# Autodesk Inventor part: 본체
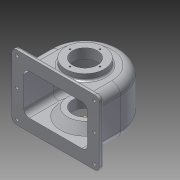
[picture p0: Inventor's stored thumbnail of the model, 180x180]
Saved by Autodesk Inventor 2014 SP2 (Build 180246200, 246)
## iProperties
Created: 2015-09
Part Number: 본체
Material: 알루미늄 6061
Document SubType Name: Modeling
Designer: 201-01
Density: 2.71 g/cm^3
Appearance: 알루미늄 - 평지
Mass: 756.01 g
Surface Area: 887.831 cm^2
Volume: 278.97 cm^3
Author: 201-01
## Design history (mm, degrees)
sketch "스케치1"
  geometry: L1 (-79.8, 0)-(79.8, 0) reference; L2 (0, -67.8)-(0, 77.8) reference; L3 (57, 0)-(57, -47); L4 (57, -47)-(-57, -47); L5 (-57, -47)-(-57, 0); A1 r 57 centre (0, 0) between (57, 0) and (-57, 0); 1 further point
  constraints: 6 end point, 2 coincident, 2 parallel, 2 point on circle, 2 tangent, 1 centre point, 1 perpendicular
  dimensions: "d1" = 47 distance of L3.start L3.end; "d2" = 57 radius of A1
extrude "돌출1" new body sketch "스케치1" distance "d3" = 77; taper "d4" = 0 deg
feature "쉘1" dims "d5" = 6
sketch "스케치2"
  geometry: C1 r 31 at (0, 0); 1 further point
  constraints: 1 centre point, 1 coincident
  dimensions: "d6" = 62 diameter of C1
extrude "돌출2" join sketch "스케치2" distance "d7" = 10; taper "d8" = 0 deg
hole "구멍1" diameter "d11" = 40; stored, may be unused: countersink angle "d15" = 90 deg, drill point angle "d17" = 0 deg; dims "d9" = 10, "d10" = 10, "d12" = 6, "d13" = 4, "d14" = 2, "d16" = 20
sketch "스케치3"
  geometry: C1 r 28 at (0, 0); 1 further point
  constraints: 1 centre point, 1 coincident
  dimensions: "d18" = 56 diameter of C1
extrude "돌출3" join sketch "스케치3" distance "d19" = 19; taper "d20" = 0 deg
feature "면 기울기2" dims angle "d47" = 40 deg
hole "구멍2" diameter "d50" = 40; stored, may be unused: countersink angle "d54" = 90 deg, drill point angle "d56" = 0 deg; dims "d48" = 10, "d49" = 10, "d51" = 6, "d52" = 4, "d53" = 2, "d55" = 20
hole "구멍3" diameter "d59" = 66; stored, may be unused: countersink angle "d63" = 90 deg, drill point angle "d65" = 0 deg; dims "d60" = 6, "d61" = 4, "d62" = 2, "d64" = 5, "d66" = 10, "d67" = 10
feature "면 기울기3" dims angle "d68" = 40 deg
sketch "스케치7"
  geometry: C1 r 33 at (0, 0) reference; 1 further point
extrude "돌출4" join sketch "스케치7" distance "d69" = 2; taper "d70" = 0 deg
sketch "스케치8"
  geometry: 1 further point
sketch "스케치9"
  geometry: C1 r 20 at (0, 0); 1 further point
  constraints: 2 coincident, 1 centre point
  dimensions: "d71" = 40 diameter of C1
extrude "돌출5" cut sketch "스케치9" distance "d72" = 4; taper "d73" = 0 deg
sketch "스케치11"
  geometry: L1 (-13, -13.5)-(127, -13.5); L2 (127, -13.5)-(127, 90.5); L3 (127, 90.5)-(-13, 90.5); L4 (-13, 90.5)-(-13, -13.5); L5 (0, 0)-(0, 77) reference; L6 (114, 0)-(114, 77) reference; L7 (57, -34.3)-(57, 111.3) reference; L8 (114, 0)-(0, 0) reference; L9 (0, 77)-(114, 77) reference; 3 further points
  constraints: 8 end point, 2 midpoint, 2 parallel, 1 horizontal, 1 perpendicular, 1 vertical alignment
  dimensions: "d75" = 104 distance of L3.end L1.start; "d76" = 140 distance of L1.start L1.end; "d77" = 13.5 distance between parallel lines of L1 L8
extrude "돌출6" join sketch "스케치11" distance "d78" = 7; taper "d79" = 0 deg
node "작업 평면2"
sketch "스케치12"
  geometry: L1 (70, 90.5)-(-70, 90.5) reference; L2 (-70, 90.5)-(-70, -13.5) reference; L3 (-70, -13.5)-(70, -13.5) reference; L4 (70, -13.5)-(70, 90.5) reference; C1 r 6 at (0, 38.5); 1 further point
  constraints: 1 centre point
  dimensions: "d82" = 12 diameter of C1; "d83" = 70 distance from line of L2 C1.centre; "d84" = 52 distance from line of L1 C1.centre
extrude "돌출7" join sketch "스케치12" stored distance "d85" = 7; taper "d86" = 0 deg
feature "면 기울기4" dims angle "d87" = 10 deg
fillet "모깎기1" dims "d88" = 14
fillet "모깎기2" dims "d89" = 7
fillet "모깎기3" dims "d90" = 1
fillet "모깎기4" dims "d91" = 3
fillet "모깎기5" dims "d92" = 3
hole "구멍4" diameter "d95" = 4.134; stored, may be unused: countersink angle "d99" = 90 deg, drill point angle "d101" = 118 deg; dims "d96" = 20, "d97" = 4, "d98" = 2, "d100" = 3, "d146" = 10, "d147" = 10
sketch "스케치13" dims "d102" = 56
  geometry: 3 further points
  constraints: 2 coincident, 1 vertical alignment, 2 other
hole "구멍5" sketch "스케치13" at (0, 28) diameter "d103" = 2.459; stored, may be unused: countersink angle "d107" = 90 deg, drill point angle "d109" = 118 deg; dims "d104" = 7, "d105" = 4, "d106" = 2, "d108" = 9
sketch "스케치14" dims "d113" = 48
  geometry: 3 further points
  constraints: 1 coincident, 1 vertical alignment, 2 other
hole "구멍6" sketch "스케치14" at (0, 24) diameter "d114" = 2.459; stored, may be unused: countersink angle "d118" = 90 deg, drill point angle "d120" = 118 deg; dims "d115" = 6, "d116" = 4, "d117" = 2, "d119" = 8
sketch "스케치15"
  geometry: L1 (-13, 6.5)-(-13, -83.5) reference; L2 (120, 13.5)-(-6, 13.5) reference; L3 (57, 34.3)-(57, -111.3) reference; L4 (57, -38.5)-(-20.152, -38.5); C1 r 2.5 at (-5, 5.5); C2 r 2.5 at (119, 5.5); C3 r 2.5 at (-5, -82.5); C4 r 2.5 at (119, -82.5); C5 r 2.5 at (-5, -38.5); C6 r 2.5 at (119, -38.5); 1 further point
  constraints: 6 centre point, 4 symmetric about line, 2 end point, 1 midpoint, 1 perpendicular, 4 other
  dimensions: "d124" = 5 diameter of C1; "d125" = 8 distance from line of L1 C1.centre; "d126" = 8 distance from line of C1.centre L2; "d138" = 5 diameter of C5; "d139" = 0 vertical distance of L4.end C5.centre; "d140" = 8 distance from line of L1 C5.centre
sketch "스케치16"
  geometry: L1 (69.5, -47)-(-20.5, -47) reference; L2 (-14, 0)-(-14, -39) reference; 1 further point
  constraints: 1 other
  dimensions: "d134" = 30 distance from line of point (24.5, -17) L1; "d135" = 38.5 distance from line of point (24.5, -17) L2
feature "엠보싱1" sketch "스케치16" dims "d18" = 56, "d136" = 0.5, "d137" = 0
extrude "돌출10" cut sketch "스케치15" stored distance "d141" = 7; taper "d142" = 0 deg
fillet "모깎기6" dims "d143" = 9
fillet "모깎기7" dims "d144" = 3
fillet "모깎기8" dims "d145" = 0.5
node "솔리드1"
pattern_circular "원형 패턴1" dims angle "d111" = 360 deg
pattern_circular "원형 패턴2" dims angle "d122" = 360 deg
other parameters: "d0" = 57, "d80" = 63
